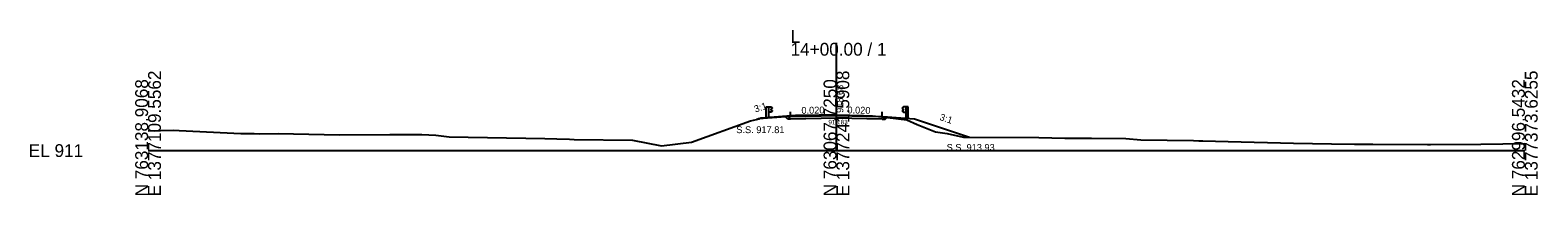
# Model space of a CAD drawing. Extents: x -26 to 303, y -10 to 6523.
# Drawn here: x -25.7 to 302.8, y 3990.3 to 4026.3 of the extents above; entities that cross this region are included whole.
import ezdxf

# ---------------------------------------------------------------- set-up
doc = ezdxf.new("R2010")
doc.units = 0
for name, color, linetype in [('Exist Cross Section Cell', 7, 'Continuous'), ('Exist XS Center Line Elevation Label', 7, 'Continuous'), ('Exist XS Ground Line', 7, 'Continuous'), ('Prop XS Dump Level', 7, 'Continuous'), ('Prop XS Elevation Labels', 7, 'Continuous'), ('Prop XS EOT Tick Mark', 7, 'Continuous'), ('Prop XS Finish Grade', 7, 'Continuous'), ('Prop XS Finish Grade Earthwork', 7, 'Continuous'), ('Prop XS Finish Grade Pavement', 7, 'Continuous'), ('Prop XS Guardrail', 7, 'Continuous'), ('Prop XS Pvmt Edge Slope', 7, 'Continuous'), ('Prop XS SE Text', 7, 'Continuous'), ('Prop XS Side Slope Text', 7, 'Continuous'), ('Prop XS SS Elevation Text', 7, 'Continuous'), ('Prop XS Subgrade Earthwork', 7, 'Continuous')]:
    doc.layers.add(name, color=color, linetype=linetype)

msp = doc.modelspace()

# ---------------------------------------------------------------- linework, layer by layer
at = {"layer": 'Exist Cross Section Cell'}
for p, q in [((150, 4000), (150, 4023.54)), ((0, 4000), (150, 4000)), ((150, 4000), (300, 4000))]:
    msp.add_line(p, q, dxfattribs=at)
at = {"layer": 'Exist XS Ground Line'}
for p, q in [((118.44, 4001.82), (131.28, 4006.47)), ((131.28, 4006.47), (133.22, 4006.94)), ((133.22, 4006.94), (133.53, 4007.18)), ((133.53, 4007.18), (134.53, 4007.25)), ((134.53, 4007.25), (141.11, 4007.75)), ((141.11, 4007.75), (143.14, 4007.77)), ((143.14, 4007.77), (149.35, 4007.85)), ((149.35, 4007.85), (150, 4007.83)), ((150, 4007.83), (155.93, 4007.68)), ((155.93, 4007.68), (157.87, 4007.63)), ((157.87, 4007.63), (161.12, 4007.25)), ((161.12, 4007.25), (165.37, 4006.73)), ((165.37, 4006.73), (167.56, 4005.73)), ((167.56, 4005.73), (171.59, 4004.1)), ((0, 4004.32), (5.44, 4004.44)), ((5.44, 4004.44), (6.8, 4004.39)), ((6.8, 4004.39), (20.21, 4003.74)), ((20.21, 4003.74), (21.65, 4003.73)), ((21.65, 4003.73), (23.09, 4003.71)), ((23.09, 4003.71), (24.22, 4003.66)), ((24.22, 4003.66), (28.33, 4003.74)), ((28.33, 4003.74), (41.68, 4003.44)), ((41.68, 4003.44), (52.71, 4003.5)), ((52.71, 4003.5), (55.67, 4003.48)), ((55.67, 4003.48), (58.18, 4003.53)), ((58.18, 4003.53), (59.66, 4003.49)), ((59.66, 4003.49), (62.7, 4003.38)), ((62.7, 4003.38), (65.6, 4003.02)), ((65.6, 4003.02), (86.46, 4002.67)), ((86.46, 4002.67), (89.07, 4002.58)), ((89.07, 4002.58), (91.85, 4002.46)), ((91.85, 4002.46), (92.83, 4002.42)), ((92.83, 4002.42), (105.56, 4002.26)), ((105.56, 4002.26), (111.86, 4001.01)), ((111.86, 4001.01), (118.44, 4001.82)), ((171.59, 4004.1), (174.15, 4003.7)), ((174.15, 4003.7), (177.69, 4002.91)), ((177.69, 4002.91), (178.07, 4002.94)), ((178.07, 4002.94), (178.71, 4002.93)), ((178.71, 4002.93), (194.07, 4002.86)), ((194.07, 4002.86), (199.74, 4002.71)), ((199.74, 4002.71), (205.61, 4002.71)), ((205.61, 4002.71), (213.06, 4002.67)), ((213.06, 4002.67), (216.34, 4002.33)), ((216.34, 4002.33), (227.79, 4002.17)), ((227.79, 4002.17), (228.97, 4002.15)), ((228.97, 4002.15), (229.86, 4002.14)), ((229.86, 4002.14), (235.39, 4001.96)), ((235.39, 4001.96), (249.61, 4001.6)), ((249.61, 4001.6), (257.84, 4001.51)), ((290.45, 4001.39), (300, 4001.53)), ((257.84, 4001.51), (262.89, 4001.4)), ((262.89, 4001.4), (266.86, 4001.38)), ((266.86, 4001.38), (278.77, 4001.33)), ((278.77, 4001.33), (279.43, 4001.32)), ((279.43, 4001.32), (290.45, 4001.39))]:
    msp.add_line(p, q, dxfattribs=at)
at = {"layer": 'Prop XS Dump Level'}
for p, q in [((140, 4007.48), (150, 4007.68)), ((150, 4007.68), (160, 4007.48))]:
    msp.add_line(p, q, dxfattribs=at)
at = {"layer": 'Prop XS EOT Tick Mark'}
for p, q in [((140, 4007.48), (140, 4008.48)), ((160, 4007.48), (160, 4008.48))]:
    msp.add_line(p, q, dxfattribs=at)
at = {"layer": 'Prop XS Finish Grade'}
for p, q in [((140, 4007.48), (138.9, 4007.39)), ((160, 4007.48), (161.1, 4007.39))]:
    msp.add_line(p, q, dxfattribs=at)
at = {"layer": 'Prop XS Finish Grade Earthwork'}
for p, q in [((133, 4006.92), (132.65, 4006.81)), ((137, 4007.24), (133, 4006.92)), ((138.9, 4007.39), (137, 4007.24)), ((161.1, 4007.39), (163, 4007.24)), ((163, 4007.24), (167, 4006.92)), ((167, 4006.92), (178.99, 4002.93))]:
    msp.add_line(p, q, dxfattribs=at)
at = {"layer": 'Prop XS Finish Grade Pavement'}
for p, q in [((140, 4007.48), (150, 4007.68)), ((150, 4007.68), (160, 4007.48))]:
    msp.add_line(p, q, dxfattribs=at)
at = {"layer": 'Prop XS Guardrail'}
for p, q in [((134.68, 4009.56), (135.18, 4009.56)), ((134.68, 4007.06), (134.68, 4009.56)), ((135.18, 4009.56), (135.68, 4009.56)), ((135.18, 4009.56), (135.18, 4007.06)), ((135.68, 4008.42), (135.18, 4008.42)), ((135.68, 4009.56), (135.97, 4009.36)), ((135.97, 4009.24), (135.68, 4009.04)), ((135.68, 4009.04), (135.68, 4008.94)), ((135.68, 4008.94), (135.97, 4008.74)), ((135.97, 4008.62), (135.68, 4008.42)), ((135.97, 4009.36), (136, 4009.3)), ((136, 4009.3), (135.97, 4009.24)), ((135.97, 4008.74), (136, 4008.68)), ((136, 4008.68), (135.97, 4008.62)), ((164.34, 4009.33), (164.31, 4009.27)), ((164.31, 4009.27), (164.34, 4009.21)), ((164.34, 4008.72), (164.31, 4008.66)), ((164.31, 4008.66), (164.34, 4008.6)), ((164.63, 4009.53), (164.34, 4009.33)), ((164.34, 4009.21), (164.63, 4009.01)), ((164.63, 4008.92), (164.34, 4008.72)), ((164.34, 4008.6), (164.63, 4008.4)), ((165.13, 4009.53), (164.63, 4009.53)), ((164.63, 4009.01), (164.63, 4008.92)), ((164.63, 4008.4), (165.13, 4008.4)), ((165.63, 4009.53), (165.13, 4009.53)), ((165.13, 4009.53), (165.13, 4007.03)), ((165.63, 4007.03), (165.63, 4009.53))]:
    msp.add_line(p, q, dxfattribs=at)
at = {"layer": 'Prop XS Pvmt Edge Slope'}
for p, q in [((140, 4007.48), (139.4, 4006.89)), ((160, 4007.48), (160.6, 4006.89))]:
    msp.add_line(p, q, dxfattribs=at)
at = {"layer": 'Prop XS Subgrade Earthwork'}
for p, q in [((139.4, 4006.89), (138.9, 4007.39)), ((140, 4006.9), (139.4, 4006.89)), ((150, 4007.1), (140, 4006.9)), ((160, 4006.9), (150, 4007.1)), ((160, 4006.9), (160.6, 4006.89)), ((160.6, 4006.89), (161.1, 4007.39))]:
    msp.add_line(p, q, dxfattribs=at)

# ---------------------------------------------------------------- texts
at = {"layer": 'Exist Cross Section Cell'}
for s, p in [('L', (140, 4023.54)), ('14+00.00 / 1', (140, 4020.74)), ('EL 911', (-26, 3998.6))]:
    msp.add_text(s, height=2.8, dxfattribs=at).set_placement(p)
for s, p in [('N 763138.9068', (0, 3990)), ('E 1377109.5562', (2.8, 3990)), ('N 763067.7250', (150, 3990)), ('E 1377241.5908', (152.8, 3990)), ('N 762996.5432', (300, 3990)), ('E 1377373.6255', (302.8, 3990))]:
    msp.add_text(s, height=2.8, rotation=90, dxfattribs=at).set_placement(p)
at = {"layer": 'Exist XS Center Line Elevation Label'}
msp.add_text('918.83', height=0.998, dxfattribs=at).set_placement((148.24, 4005.72))
at = {"layer": 'Prop XS Dump Level'}
for p in [(137, 4007.2), (163, 4007.2)]:
    msp.add_text('Case1', height=0.04, dxfattribs=at).set_placement(p)
at = {"layer": 'Prop XS Elevation Labels'}
msp.add_text(' 918.68', height=1.5, rotation=90, dxfattribs=at).set_placement((151.5, 4007.68))
at = {"layer": 'Prop XS SE Text'}
for rotation, p in [(1.1458, (142.38, 4008.03)), (358.8542, (152.38, 4008.13))]:
    msp.add_text('0.020', height=1.5, rotation=rotation, dxfattribs=at).set_placement(p)
at = {"layer": 'Prop XS Side Slope Text'}
for rotation, p in [(18.4349, (132.35, 4008.29)), (341.5651, (172.36, 4006.72))]:
    msp.add_text('3:1', height=1.5, rotation=rotation, dxfattribs=at).set_placement(p)
at = {"layer": 'Prop XS SS Elevation Text'}
for s, p in [('S.S. 917.81', (128.19, 4003.81)), ('S.S. 913.93', (174.01, 3999.94))]:
    msp.add_text(s, height=1.5, dxfattribs=at).set_placement(p)

doc.saveas('drawing.dxf')
